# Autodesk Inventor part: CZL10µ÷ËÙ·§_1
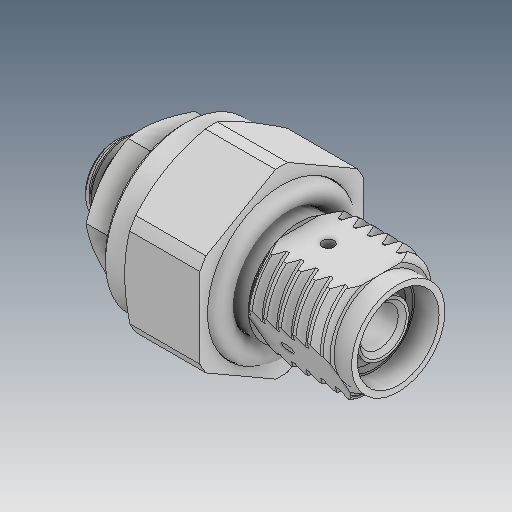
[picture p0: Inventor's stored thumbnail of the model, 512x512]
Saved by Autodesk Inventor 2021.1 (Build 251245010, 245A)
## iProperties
Created: 2019-05
Part Number: CZL10µ÷ËÙ·§_1
Material: Ogólny
Document SubType Name: Modeling
Designer: user
Density: 1 g/cm^3
Appearance: Domyślna
Author: user
Revision Number: ÈÎºÎ
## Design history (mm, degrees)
feature "ÊäÈë1"
feature "ÊäÈë2"
feature "ÊäÈë3"
node "Bryła1"
node "Bryła2"
node "Bryła3"
